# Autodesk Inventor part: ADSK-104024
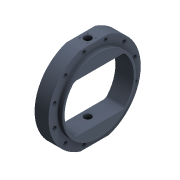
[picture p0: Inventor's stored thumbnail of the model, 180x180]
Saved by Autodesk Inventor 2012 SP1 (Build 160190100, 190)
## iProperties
Shininess: 0.0
Created: 2000-09
Part Number: ADSK-104024
Document SubType Name: Modeling
Stock Number: ADSK-104024
Density: 1 g/cm^3
Material: Default
Density: 0.0
Volumn: 0.0
Area: 0.0
PropertySet Name: Model Information
Control State: 0
Master: False
Checked Out: False
Author: gao
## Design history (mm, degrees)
node "Revolution1" dims "d4" = 360 deg
  sketch "Sketch1"
    geometry: L1 (-12.56, 99.738)-(25.54, 99.738); L2 (38.24, 74.338)-(38.24, -27.262); L3 (38.24, -27.262)-(-12.56, -27.262); L4 (-12.56, -27.262)-(-12.56, 99.738); L5 (25.54, 99.738)-(25.54, 74.338); L6 (25.54, 74.338)-(38.24, 74.338)
    constraints: 12 end point, 3 parallel, 2 perpendicular, 1 horizontal
    dimensions: "d0" = 127 distance of L3.end L1.start; "d1" = 50.8 distance of L2.end L3.end; "d2" = 101.6 distance between parallel lines of L3 L6; "d3" = 12.7 distance of L5.end L2.start
workplane "Work Plane2"
node "Hole1" dims "d15" = 20, "d16" = 9.525, "d17" = 6.35, "d18" = 60 deg, "d19" = 19.05, "d20" = 118 deg
  sketch "Sketch4"
    geometry: L1 (19.05, 127)-(19.05, -127) reference; L2 (19.05, -127)-(-19.05, -127) reference; 1 further point
    dimensions: "d14" = 19.05 distance from line of point (0, 0) L1; "d23" = 127 distance from line of point (0, 0) L2 (= d0)
node "Extrusion2" dims "d21" = 6.35, "d22" = 0
  sketch "Sketch5"
    geometry: L1 (19.05, 127)-(19.05, -127) reference; L2 (-19.05, 101.6)-(-19.05, -101.6) reference; L3 (19.05, 127)-(-19.05, 127) reference; L4 (19.05, 127)-(-19.05, 127); L5 (-19.05, -127)-(-19.05, 127); L6 (-16.433, -127)-(19.05, -127); L7 (19.05, 122.783)-(19.05, -127); L8 (19.05, -127)-(-19.05, -127)
    constraints: 10 end point, 2 collinear, 2 perpendicular, 1 point on line
node "Extrusion3" dims "d45" = 6.35, "d46" = 0
  sketch "Sketch10"
    geometry: L1 (39.656, 120.65)-(-39.656, 120.65) reference; L2 (-68.022, 66.675)-(68.022, 66.675); L3 (-68.022, -66.675)-(68.022, -66.675); A1 r 127 centre (0, 0) between (-39.656, 120.65) and (39.656, 120.65) reference; A2 r 95.25 centre (0, 0) between (-68.022, 66.675) and (-68.022, -66.675); A3 r 95.25 centre (0, 0) between (68.022, -66.675) and (68.022, 66.675)
    constraints: 4 end point, 4 point on circle, 2 centre point, 2 parallel, 1 coincident
    dimensions: "d43" = 66.675 distance from line of L2 A1.centre; "d44" = 66.675 distance from line of L3 A1.centre (= d43); "d47" = 95.25 radius of A3; "d48" = 95.25 radius of A2 (= d47)
node "Fillet1" dims "d49" = 12.7
node "Hole4" dims "d52" = 10.3124, "d53" = 9.525, "d54" = 6.35, "d55" = 60 deg, "d56" = 3.175, "d57" = 0
  sketch "Sketch11" dims "d50" = 228.6
    geometry: L1 (-62.46, 66.675)-(62.46, 66.675) reference; L2 (0, 0)-(38.295, 142.918); A1 r 127 centre (0, 0) between (-39.656, 120.65) and (39.656, 120.65) reference; 1 further point
    constraints: 2 end point, 1 coincident, 1 point on line, 3 other
    dimensions: "d51" = 75 deg angle of L2 L1
node "Circular Pattern2" dims "d58" = 120, "d60" = 30 deg
workaxis "Work Axis2"
workplane "Work Plane3"
node "Mirror3"
workplane "Work Plane4"
node "Hole5" dims "d62" = 14.224, "d63" = 9.525, "d64" = 6.35, "d65" = 60 deg, "d66" = 9.525, "d67" = 0
  sketch "Sketch12"
    geometry: C1 r 5.156 at (69.239, -10.245) reference; 1 further point
    constraints: 1 coincident
node "Circular Pattern3" dims "d68" = 120, "d70" = 30 deg
node "Hole6" dims "d71" = 2.6416, "d72" = 9.525, "d73" = 6.35, "d74" = 60 deg, "d75" = 19.05, "d76" = 0, "d83" = 12.7
  sketch "Sketch13"
    geometry: C1 r 3.175 at (-11.112, -11.113) reference; C2 r 3.175 at (-11.113, 11.113) reference; C3 r 3.175 at (11.113, 11.113) reference; C4 r 3.175 at (11.113, -11.113) reference; 4 further points
    constraints: 4 coincident
node "Hole7" dims "d77" = 2.6416, "d78" = 9.525, "d79" = 6.35, "d80" = 60 deg, "d81" = 19.05, "d82" = 0, "d84" = 12.7
  sketch "Sketch14"
    geometry: C1 r 3.175 at (7.937, 28.543) reference; C2 r 3.175 at (30.162, 28.543) reference; C3 r 3.175 at (30.162, 50.768) reference; C4 r 3.175 at (7.937, 50.768) reference; 4 further points
    constraints: 4 coincident
body "Solid1"
other parameters: "d42" = 196.85, "d61" = 0
